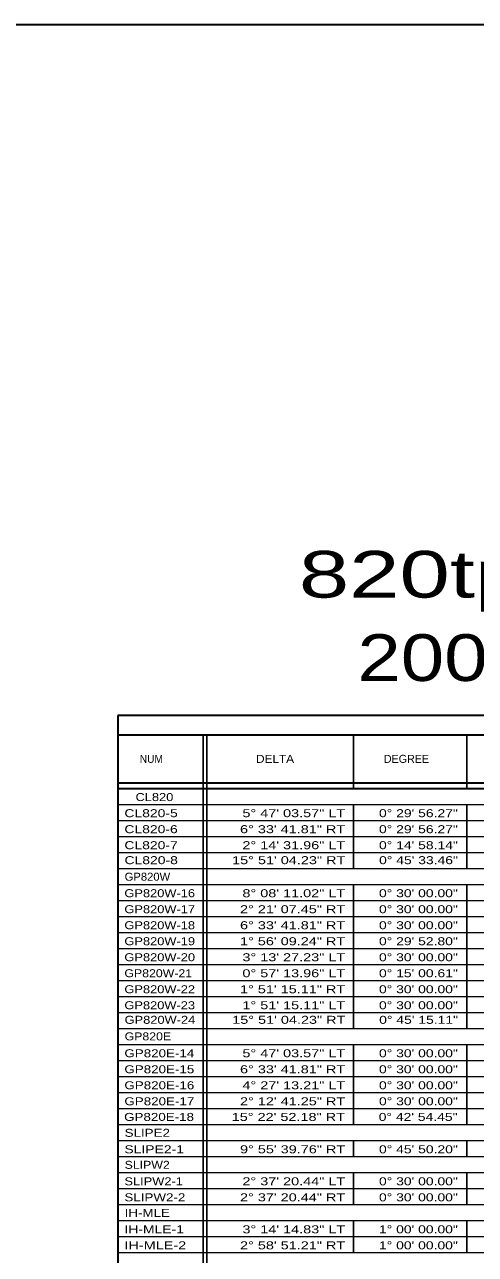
# Model space of a CAD drawing. Extents: x 1953053 to 1967065, y 7363860 to 7371201.
# Drawn here: x 1959817 to 1960493, y 7369357 to 7371201 of the extents above; entities that cross this region are included whole.
import ezdxf
from ezdxf.enums import TextEntityAlignment as Align

# ---------------------------------------------------------------- set-up
doc = ezdxf.new("R2010")
doc.units = 0
doc.header["$LTSCALE"] = 4.8
doc.layers.add('10', color=7, linetype='Continuous')
doc.layers.add('12', color=7, linetype='Continuous', lineweight=25)
doc.layers.add('62', color=7, linetype='Continuous', lineweight=35)

msp = doc.modelspace()

# ---------------------------------------------------------------- linework, layer by layer
at = {"layer": '12', "lineweight": 35}
for p, q in [((1961680.213, 7370164.879), (1959956.881, 7370164.879)), ((1959956.881, 7370164.879), (1959956.881, 7368111.747)), ((1959956.881, 7370136.079), (1961680.213, 7370136.079)), ((1959956.881, 7370064.079), (1961680.213, 7370064.079)), ((1959956.881, 7370055.746), (1961680.213, 7370055.746))]:
    msp.add_line(p, q, dxfattribs=at)
at = {"layer": '12'}
for p, q in [((1960084.726, 7370136.079), (1960084.726, 7368111.747)), ((1960090.213, 7370136.079), (1960090.213, 7368111.747)), ((1960310.213, 7370136.079), (1960310.213, 7370055.746)), ((1960480.213, 7370136.079), (1960480.213, 7370055.746)), ((1960084.726, 7370114.479), (1960084.726, 7369838.526)), ((1960310.213, 7370031.746), (1960310.213, 7369935.746)), ((1960480.213, 7370031.746), (1960480.213, 7369935.746)), ((1960310.213, 7369911.746), (1960310.213, 7369695.746)), ((1960480.213, 7369911.746), (1960480.213, 7369695.746)), ((1960310.213, 7369671.746), (1960310.213, 7369551.746)), ((1960480.213, 7369671.746), (1960480.213, 7369551.746)), ((1960310.213, 7369527.746), (1960310.213, 7369503.746)), ((1960480.213, 7369527.746), (1960480.213, 7369503.746)), ((1960310.213, 7369479.746), (1960310.213, 7369431.746)), ((1960480.213, 7369479.746), (1960480.213, 7369431.746)), ((1960310.213, 7369407.746), (1960310.213, 7369359.746)), ((1960480.213, 7369407.746), (1960480.213, 7369359.746))]:
    msp.add_line(p, q, dxfattribs=at)
at = {"layer": '12', "lineweight": 13}
for p, q in [((1959956.881, 7370007.746), (1961680.213, 7370007.746)), ((1959956.881, 7369983.746), (1961680.213, 7369983.746)), ((1959956.881, 7369959.746), (1961680.213, 7369959.746)), ((1959956.881, 7369935.746), (1961680.213, 7369935.746)), ((1959956.881, 7369911.746), (1961680.213, 7369911.746)), ((1959956.881, 7369887.746), (1961680.213, 7369887.746)), ((1959956.881, 7369863.746), (1961680.213, 7369863.746)), ((1959956.881, 7369839.746), (1961680.213, 7369839.746)), ((1959956.881, 7369815.746), (1961680.213, 7369815.746)), ((1959956.881, 7369791.746), (1961680.213, 7369791.746)), ((1959956.881, 7369767.746), (1961680.213, 7369767.746)), ((1959956.881, 7369743.746), (1961680.213, 7369743.746)), ((1959956.881, 7369719.746), (1961680.213, 7369719.746)), ((1959956.881, 7369695.746), (1961680.213, 7369695.746)), ((1959956.881, 7369647.746), (1961680.213, 7369647.746)), ((1959956.881, 7369623.746), (1961680.213, 7369623.746)), ((1959956.881, 7369599.746), (1961680.213, 7369599.746)), ((1959956.881, 7369575.746), (1961680.213, 7369575.746)), ((1959956.881, 7369551.746), (1961680.213, 7369551.746)), ((1959956.881, 7369527.746), (1961680.213, 7369527.746)), ((1959956.881, 7369503.746), (1961680.213, 7369503.746)), ((1959956.881, 7369479.746), (1961680.213, 7369479.746)), ((1959956.881, 7369455.746), (1961680.213, 7369455.746)), ((1959956.881, 7369431.746), (1961680.213, 7369431.746)), ((1959956.881, 7369407.746), (1961680.213, 7369407.746)), ((1959956.881, 7369383.746), (1961680.213, 7369383.746)), ((1959956.881, 7369359.746), (1961680.213, 7369359.746))]:
    msp.add_line(p, q, dxfattribs=at)
for points in [[(1959956.881, 7370031.746), (1960867.445, 7370031.746), (1961680.213, 7370031.746)], [(1959956.881, 7369671.746), (1961378.496, 7369671.746), (1961680.213, 7369671.746)]]:
    msp.add_lwpolyline(points, dxfattribs=at)
at = {"layer": '62'}
msp.add_lwpolyline([(1953052.784, 7371201.108), (1967065.314, 7371201.108), (1967065.314, 7363859.877), (1953052.784, 7363859.877)], close=True, dxfattribs=at)

# ---------------------------------------------------------------- texts
at = {"layer": '10'}
for s, width, p in [('CL820', 1.2, (1959983.154, 7370036.747)), ('CL820-5', 1.3, (1959966.502, 7370012.573)), ('CL820-6', 1.3, (1959966.502, 7369988.573)), ('CL820-7', 1.3, (1959966.502, 7369964.573)), ('CL820-8', 1.3, (1959966.656, 7369942.126)), ('GP820W', 1.05, (1959966.826, 7369917.332)), ('GP820W-16', 1.2, (1959966.502, 7369892.573)), ('GP820W-17', 1.2, (1959966.502, 7369868.573)), ('GP820W-18', 1.2, (1959966.502, 7369844.573)), ('GP820W-19', 1.2, (1959966.502, 7369820.573)), ('GP820W-20', 1.2, (1959966.502, 7369796.573)), ('GP820W-21', 1.15, (1959966.502, 7369772.573)), ('GP820W-22', 1.2, (1959966.502, 7369748.573)), ('GP820W-23', 1.2, (1959966.502, 7369724.573)), ('GP820W-24', 1.2, (1959966.801, 7369702.722)), ('GP820E', 1.15, (1959966.826, 7369677.908)), ('GP820E-14', 1.25, (1959966.502, 7369652.573)), ('GP820E-15', 1.25, (1959966.502, 7369628.573)), ('GP820E-16', 1.25, (1959966.502, 7369604.573)), ('GP820E-17', 1.25, (1959966.502, 7369580.573)), ('GP820E-18', 1.25, (1959966.088, 7369557.11)), ('SLIPE2', 1.25, (1959966.827, 7369533.291)), ('SLIPE2-1', 1.3, (1959966.502, 7369508.573)), ('SLIPW2', 1.15, (1959966.827, 7369485.291)), ('SLIPW2-1', 1.2, (1959966.502, 7369460.573)), ('SLIPW2-2', 1.25, (1959966.502, 7369436.573)), ('IH-MLE', 1.25, (1959966.827, 7369413.291)), ('IH-MLE-1', 1.3, (1959966.502, 7369388.573)), ('IH-MLE-2', 1.35, (1959966.502, 7369364.573))]:
    msp.add_text(s, height=12, dxfattribs=dict(at, width=width)).set_placement(p)
for s, width, p in [('5° 47\' 03.57" LT', 1.35, (1960297.735, 7370012.573)), ('0° 29\' 56.27"', 1.3, (1960466.73, 7370012.573)), ('6° 33\' 41.81" RT', 1.35, (1960297.735, 7369988.573)), ('0° 29\' 56.27"', 1.3, (1960466.73, 7369988.573)), ('2° 14\' 31.96" LT', 1.35, (1960297.735, 7369964.573)), ('0° 14\' 58.14"', 1.3, (1960466.73, 7369964.573)), ('15° 51\' 04.23" RT', 1.35, (1960297.889, 7369942.126)), ('0° 45\' 33.46"', 1.3, (1960466.884, 7369942.126)), ('8° 08\' 11.02" LT', 1.35, (1960297.735, 7369892.573)), ('0° 30\' 00.00"', 1.3, (1960466.73, 7369892.573)), ('2° 21\' 07.45" RT', 1.35, (1960297.735, 7369868.573)), ('0° 30\' 00.00"', 1.3, (1960466.73, 7369868.573)), ('6° 33\' 41.81" RT', 1.35, (1960297.735, 7369844.573)), ('0° 30\' 00.00"', 1.3, (1960466.73, 7369844.573)), ('1° 56\' 09.24" RT', 1.35, (1960297.735, 7369820.573)), ('0° 29\' 52.80"', 1.3, (1960466.73, 7369820.573)), ('3° 13\' 27.23" LT', 1.35, (1960297.735, 7369796.573)), ('0° 30\' 00.00"', 1.3, (1960466.73, 7369796.573)), ('0° 57\' 13.96" LT', 1.35, (1960297.735, 7369772.573)), ('0° 15\' 00.61"', 1.3, (1960466.73, 7369772.573)), ('1° 51\' 15.11" RT', 1.35, (1960297.735, 7369748.573)), ('0° 30\' 00.00"', 1.3, (1960466.73, 7369748.573)), ('1° 51\' 15.11" LT', 1.35, (1960297.735, 7369724.573)), ('0° 30\' 00.00"', 1.3, (1960466.73, 7369724.573)), ('15° 51\' 04.23" RT', 1.35, (1960298.034, 7369702.722)), ('0° 45\' 15.11"', 1.3, (1960467.029, 7369702.722)), ('5° 47\' 03.57" LT', 1.35, (1960297.735, 7369652.573)), ('0° 30\' 00.00"', 1.3, (1960466.73, 7369652.573)), ('6° 33\' 41.81" RT', 1.35, (1960297.735, 7369628.573)), ('0° 30\' 00.00"', 1.3, (1960466.73, 7369628.573)), ('4° 27\' 13.21" LT', 1.35, (1960297.735, 7369604.573)), ('0° 30\' 00.00"', 1.3, (1960466.73, 7369604.573)), ('2° 12\' 41.25" RT', 1.35, (1960297.735, 7369580.573)), ('0° 30\' 00.00"', 1.3, (1960466.73, 7369580.573)), ('15° 22\' 52.18" RT', 1.35, (1960297.321, 7369557.11)), ('0° 42\' 54.45"', 1.3, (1960466.316, 7369557.11)), ('9° 55\' 39.76" RT', 1.35, (1960297.735, 7369508.573)), ('0° 45\' 50.20"', 1.3, (1960466.73, 7369508.573)), ('2° 37\' 20.44" LT', 1.35, (1960297.735, 7369460.573)), ('0° 30\' 00.00"', 1.3, (1960466.73, 7369460.573)), ('2° 37\' 20.44" RT', 1.35, (1960297.735, 7369436.573)), ('0° 30\' 00.00"', 1.3, (1960466.73, 7369436.573)), ('3° 14\' 14.83" LT', 1.35, (1960297.735, 7369388.573)), ('1° 00\' 00.00"', 1.3, (1960466.73, 7369388.573)), ('2° 58\' 51.21" RT', 1.35, (1960297.735, 7369364.573)), ('1° 00\' 00.00"', 1.3, (1960466.73, 7369364.573))]:
    msp.add_text(s, height=12, dxfattribs=dict(at, width=width)).set_placement(p, align=Align.RIGHT)
at = {"layer": '12'}
for s, width, p in [('NUM', 0.95, (1960006.927, 7370094.075)), ('DELTA', 1.1, (1960192.504, 7370094.078))]:
    msp.add_text(s, height=12, dxfattribs=dict(at, width=width)).set_placement(p, align=Align.CENTER)
msp.add_text('DEGREE', height=12, dxfattribs=at).set_placement((1960389.59, 7370094.078), align=Align.CENTER)
at = {"layer": '62'}
for s, width, p in [('820tpp04.sht', 1.45, (1960620.637, 7370341.878)), ('200 SCALE', 1.25, (1960621.745, 7370216.878))]:
    msp.add_text(s, height=70, dxfattribs=dict(at, width=width)).set_placement(p, align=Align.CENTER)

doc.saveas('drawing.dxf')
